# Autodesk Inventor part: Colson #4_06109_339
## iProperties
Shininess: 64.0
Length Units: 11272
Angle Units: 11279
Time Units: 11290
Mass Units: 11286
Length Display Precision: 3
Angle Display Precision: 2
Compacted: True
Part Number: Colson #4_06109_339
Document SubType Name: Modeling
Created: 2003-06
Designer: ARennick
Manufacturer: Standard
Standards Organization: Custom
Description: Series 4 (1250lb) Swivel Caster, Standard Mount Plate, 6 dia, Phenolic wheel.
Catalog Web Link: www.colsoncaster.com
Density: 0.0
Volumn: 0.0
Area: 0.0
PropertySet Name: Model Information
Control State: 0
Master: False
Checked Out: False
Author: ARennick
Comments: These are basically 5 sizes of caster with different part numbers used for the materials. This file allows you to specify the wheel angle, but you also must specify a filename upon placement. Thanks a
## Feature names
1. Top Plate [Extrusion]
2. Bearing Shape [Revolution]
3. Bearing Fillets [Fillet]
4. Wheel Flange Cut [Extrusion]
5. Extrusion5
6. Extrusion6
7. Mirror2
8. Revolution2
9. Fillet2
